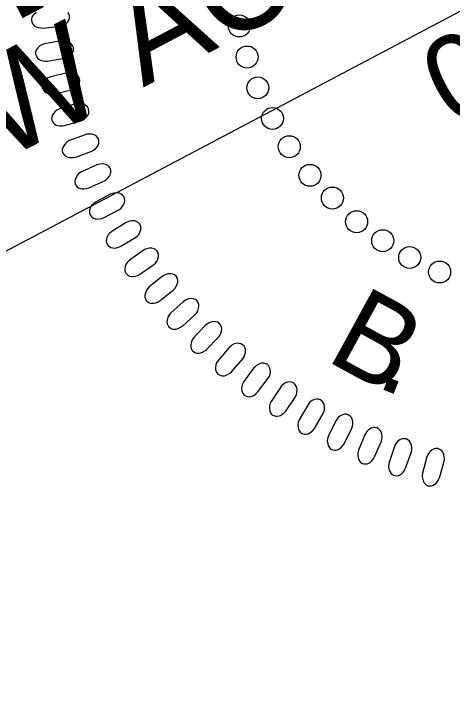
# Model space of a CAD drawing. Extents: x 1486990 to 1489232, y 497582 to 499336.
# Drawn here: x 1488502.11 to 1488528, y 499157.88 to 499198.76 of the extents above; entities that cross this region are included whole.
import ezdxf

# ---------------------------------------------------------------- set-up
doc = ezdxf.new("R2010")
doc.units = 0
doc.layers.add('PROF-MAJR', color=7, linetype='Continuous')
doc.layers.add('Prop Drainage Structure Drop Inlet Adjust CELL', color=7, linetype='Continuous')

msp = doc.modelspace()

# ---------------------------------------------------------------- linework, layer by layer
at = {"layer": 'PROF-MAJR'}
msp.add_lwpolyline([(1488503.435, 499198.848), (1488503.308, 499198.743), (1488503.228, 499198.655), (1488503.174, 499198.558), (1488503.152, 499198.47), (1488503.145, 499198.377), (1488503.171, 499198.289), (1488503.206, 499198.195), (1488503.263, 499198.116), (1488503.352, 499198.041), (1488503.422, 499198), (1488503.548, 499197.959), (1488503.698, 499197.927), (1488503.829, 499197.922), (1488504.841, 499198.027), (1488504.975, 499198.06), (1488505.084, 499198.109), (1488505.204, 499198.194), (1488505.307, 499198.297), (1488505.363, 499198.382), (1488505.398, 499198.514), (1488505.4, 499198.636), (1488505.355, 499198.753), (1488505.305, 499198.833)], dxfattribs=at)
for points in [[(1488504.905, 499197.16), (1488503.926, 499196.99), (1488503.756, 499196.93), (1488503.652, 499196.869), (1488503.532, 499196.757), (1488503.458, 499196.663), (1488503.41, 499196.563), (1488503.393, 499196.474), (1488503.392, 499196.382), (1488503.424, 499196.295), (1488503.464, 499196.204), (1488503.526, 499196.129), (1488503.62, 499196.059), (1488503.693, 499196.022), (1488503.821, 499195.989), (1488503.972, 499195.966), (1488504.103, 499195.97), (1488505.107, 499196.138), (1488505.239, 499196.18), (1488505.344, 499196.235), (1488505.459, 499196.329), (1488505.555, 499196.437), (1488505.606, 499196.526), (1488505.632, 499196.659), (1488505.627, 499196.781), (1488505.574, 499196.895), (1488505.52, 499196.972), (1488505.423, 499197.06), (1488505.271, 499197.132), (1488505.118, 499197.16), (1488505.01, 499197.166)], [(1488505.254, 499195.278), (1488504.288, 499195.047), (1488504.122, 499194.977), (1488504.021, 499194.909), (1488503.909, 499194.789), (1488503.841, 499194.692), (1488503.799, 499194.588), (1488503.788, 499194.499), (1488503.793, 499194.406), (1488503.829, 499194.322), (1488503.876, 499194.233), (1488503.943, 499194.162), (1488504.041, 499194.099), (1488504.115, 499194.066), (1488504.246, 499194.041), (1488504.398, 499194.028), (1488504.528, 499194.04), (1488505.52, 499194.271), (1488505.649, 499194.321), (1488505.751, 499194.382), (1488505.859, 499194.483), (1488505.948, 499194.597), (1488505.993, 499194.689), (1488506.011, 499194.824), (1488505.998, 499194.946), (1488505.938, 499195.056), (1488505.879, 499195.129), (1488505.777, 499195.21), (1488505.621, 499195.273), (1488505.467, 499195.292), (1488505.359, 499195.291)], [(1488505.757, 499193.441), (1488504.807, 499193.15), (1488504.646, 499193.069), (1488504.55, 499192.996), (1488504.445, 499192.868), (1488504.383, 499192.767), (1488504.348, 499192.661), (1488504.342, 499192.571), (1488504.353, 499192.479), (1488504.396, 499192.397), (1488504.447, 499192.311), (1488504.518, 499192.245), (1488504.62, 499192.187), (1488504.696, 499192.16), (1488504.828, 499192.143), (1488504.981, 499192.139), (1488505.11, 499192.16), (1488506.086, 499192.452), (1488506.211, 499192.51), (1488506.309, 499192.578), (1488506.411, 499192.685), (1488506.492, 499192.805), (1488506.531, 499192.899), (1488506.54, 499193.035), (1488506.52, 499193.156), (1488506.454, 499193.262), (1488506.39, 499193.331), (1488506.283, 499193.406), (1488506.123, 499193.459), (1488505.968, 499193.468), (1488505.861, 499193.46)], [(1488506.332, 499191.624), (1488505.402, 499191.274), (1488505.246, 499191.183), (1488505.155, 499191.104), (1488505.059, 499190.97), (1488505.003, 499190.866), (1488504.975, 499190.758), (1488504.974, 499190.667), (1488504.991, 499190.576), (1488505.038, 499190.497), (1488505.095, 499190.415), (1488505.17, 499190.353), (1488505.276, 499190.302), (1488505.354, 499190.279), (1488505.486, 499190.271), (1488505.639, 499190.277), (1488505.767, 499190.305), (1488506.721, 499190.658), (1488506.844, 499190.724), (1488506.936, 499190.798), (1488507.032, 499190.911), (1488507.105, 499191.036), (1488507.138, 499191.133), (1488507.139, 499191.269), (1488507.111, 499191.388), (1488507.038, 499191.489), (1488506.971, 499191.555), (1488506.859, 499191.623), (1488506.696, 499191.665), (1488506.541, 499191.664), (1488506.434, 499191.65)], [(1488507.014, 499189.837), (1488506.108, 499189.43), (1488505.958, 499189.329), (1488505.872, 499189.244), (1488505.784, 499189.105), (1488505.735, 499188.996), (1488505.714, 499188.887), (1488505.719, 499188.796), (1488505.742, 499188.707), (1488505.794, 499188.631), (1488505.856, 499188.552), (1488505.934, 499188.495), (1488506.043, 499188.451), (1488506.122, 499188.433), (1488506.255, 499188.433), (1488506.407, 499188.449), (1488506.532, 499188.485), (1488507.463, 499188.898), (1488507.581, 499188.97), (1488507.669, 499189.05), (1488507.757, 499189.17), (1488507.823, 499189.298), (1488507.85, 499189.397), (1488507.842, 499189.533), (1488507.806, 499189.65), (1488507.727, 499189.747), (1488507.656, 499189.808), (1488507.54, 499189.869), (1488507.375, 499189.9), (1488507.22, 499189.891), (1488507.114, 499189.869)], [(1488507.81, 499188.104), (1488506.931, 499187.64), (1488506.789, 499187.531), (1488506.708, 499187.441), (1488506.629, 499187.296), (1488506.587, 499187.185), (1488506.573, 499187.074), (1488506.584, 499186.985), (1488506.612, 499186.896), (1488506.669, 499186.824), (1488506.735, 499186.75), (1488506.817, 499186.697), (1488506.929, 499186.66), (1488507.008, 499186.647), (1488507.141, 499186.656), (1488507.292, 499186.681), (1488507.415, 499186.725), (1488508.318, 499187.195), (1488508.431, 499187.275), (1488508.514, 499187.36), (1488508.594, 499187.485), (1488508.652, 499187.618), (1488508.672, 499187.718), (1488508.656, 499187.853), (1488508.613, 499187.967), (1488508.528, 499188.059), (1488508.453, 499188.115), (1488508.334, 499188.169), (1488508.167, 499188.19), (1488508.013, 499188.17), (1488507.908, 499188.143)], [(1488508.74, 499186.436), (1488507.892, 499185.918), (1488507.756, 499185.799), (1488507.682, 499185.704), (1488507.612, 499185.555), (1488507.577, 499185.441), (1488507.569, 499185.33), (1488507.586, 499185.241), (1488507.62, 499185.155), (1488507.681, 499185.087), (1488507.753, 499185.016), (1488507.837, 499184.969), (1488507.951, 499184.939), (1488508.031, 499184.931), (1488508.163, 499184.948), (1488508.312, 499184.983), (1488508.432, 499185.034), (1488509.304, 499185.56), (1488509.411, 499185.647), (1488509.488, 499185.737), (1488509.561, 499185.867), (1488509.61, 499186.003), (1488509.625, 499186.104), (1488509.6, 499186.238), (1488509.55, 499186.349), (1488509.459, 499186.436), (1488509.381, 499186.487), (1488509.258, 499186.533), (1488509.091, 499186.544), (1488508.938, 499186.515), (1488508.836, 499186.48)], [(1488509.759, 499184.793), (1488508.945, 499184.223), (1488508.818, 499184.096), (1488508.749, 499183.996), (1488508.689, 499183.843), (1488508.661, 499183.727), (1488508.66, 499183.616), (1488508.683, 499183.528), (1488508.722, 499183.444), (1488508.787, 499183.38), (1488508.862, 499183.314), (1488508.95, 499183.272), (1488509.066, 499183.25), (1488509.147, 499183.247), (1488509.276, 499183.272), (1488509.424, 499183.316), (1488509.54, 499183.375), (1488510.377, 499183.954), (1488510.479, 499184.048), (1488510.55, 499184.143), (1488510.615, 499184.276), (1488510.655, 499184.415), (1488510.663, 499184.517), (1488510.629, 499184.649), (1488510.573, 499184.757), (1488510.477, 499184.838), (1488510.395, 499184.884), (1488510.27, 499184.923), (1488510.102, 499184.923), (1488509.952, 499184.883), (1488509.852, 499184.843)], [(1488510.878, 499183.254), (1488510.102, 499182.633), (1488509.982, 499182.499), (1488509.919, 499182.396), (1488509.869, 499182.238), (1488509.849, 499182.121), (1488509.855, 499182.01), (1488509.883, 499181.924), (1488509.927, 499181.843), (1488509.996, 499181.782), (1488510.076, 499181.722), (1488510.166, 499181.685), (1488510.282, 499181.67), (1488510.363, 499181.672), (1488510.492, 499181.705), (1488510.636, 499181.758), (1488510.748, 499181.825), (1488511.547, 499182.456), (1488511.643, 499182.556), (1488511.708, 499182.655), (1488511.764, 499182.792), (1488511.796, 499182.934), (1488511.797, 499183.035), (1488511.756, 499183.165), (1488511.692, 499183.27), (1488511.592, 499183.344), (1488511.507, 499183.385), (1488511.38, 499183.415), (1488511.212, 499183.405), (1488511.064, 499183.356), (1488510.968, 499183.31)], [(1488512.107, 499181.759), (1488511.371, 499181.091), (1488511.261, 499180.949), (1488511.205, 499180.842), (1488511.164, 499180.682), (1488511.151, 499180.564), (1488511.165, 499180.453), (1488511.198, 499180.369), (1488511.247, 499180.291), (1488511.32, 499180.235), (1488511.403, 499180.179), (1488511.495, 499180.149), (1488511.613, 499180.14), (1488511.693, 499180.148), (1488511.819, 499180.189), (1488511.96, 499180.251), (1488512.067, 499180.324), (1488512.825, 499181.004), (1488512.915, 499181.11), (1488512.974, 499181.213), (1488513.021, 499181.353), (1488513.043, 499181.496), (1488513.038, 499181.598), (1488512.989, 499181.725), (1488512.919, 499181.826), (1488512.814, 499181.893), (1488512.727, 499181.929), (1488512.598, 499181.951), (1488512.432, 499181.93), (1488512.287, 499181.873), (1488512.193, 499181.82)], [(1488513.44, 499180.37), (1488512.748, 499179.658), (1488512.646, 499179.509), (1488512.596, 499179.399), (1488512.566, 499179.237), (1488512.561, 499179.118), (1488512.581, 499179.008), (1488512.619, 499178.926), (1488512.673, 499178.851), (1488512.75, 499178.8), (1488512.836, 499178.75), (1488512.93, 499178.725), (1488513.048, 499178.725), (1488513.127, 499178.737), (1488513.251, 499178.786), (1488513.387, 499178.857), (1488513.49, 499178.936), (1488514.204, 499179.662), (1488514.286, 499179.774), (1488514.339, 499179.88), (1488514.377, 499180.023), (1488514.39, 499180.167), (1488514.379, 499180.269), (1488514.321, 499180.392), (1488514.246, 499180.488), (1488514.137, 499180.549), (1488514.048, 499180.58), (1488513.918, 499180.593), (1488513.753, 499180.562), (1488513.612, 499180.496), (1488513.522, 499180.437)], [(1488514.83, 499179.056), (1488514.183, 499178.301), (1488514.091, 499178.146), (1488514.049, 499178.032), (1488514.029, 499177.869), (1488514.031, 499177.75), (1488514.058, 499177.642), (1488514.101, 499177.563), (1488514.16, 499177.491), (1488514.239, 499177.445), (1488514.329, 499177.4), (1488514.424, 499177.381), (1488514.541, 499177.388), (1488514.62, 499177.405), (1488514.741, 499177.462), (1488514.872, 499177.541), (1488514.97, 499177.627), (1488515.637, 499178.396), (1488515.712, 499178.513), (1488515.758, 499178.622), (1488515.787, 499178.768), (1488515.791, 499178.913), (1488515.774, 499179.013), (1488515.708, 499179.133), (1488515.627, 499179.224), (1488515.514, 499179.278), (1488515.423, 499179.302), (1488515.293, 499179.308), (1488515.13, 499179.266), (1488514.994, 499179.191), (1488514.907, 499179.127)], [(1488516.291, 499177.85), (1488515.694, 499177.055), (1488515.611, 499176.895), (1488515.577, 499176.779), (1488515.567, 499176.615), (1488515.576, 499176.497), (1488515.61, 499176.39), (1488515.658, 499176.314), (1488515.721, 499176.246), (1488515.803, 499176.205), (1488515.896, 499176.166), (1488515.992, 499176.153), (1488516.109, 499176.167), (1488516.186, 499176.189), (1488516.303, 499176.253), (1488516.429, 499176.341), (1488516.521, 499176.433), (1488517.138, 499177.242), (1488517.206, 499177.364), (1488517.245, 499177.475), (1488517.265, 499177.622), (1488517.261, 499177.767), (1488517.236, 499177.867), (1488517.164, 499177.982), (1488517.076, 499178.068), (1488516.96, 499178.114), (1488516.868, 499178.133), (1488516.737, 499178.131), (1488516.578, 499178.079), (1488516.446, 499177.995), (1488516.364, 499177.926)], [(1488517.855, 499176.707), (1488517.308, 499175.877), (1488517.236, 499175.712), (1488517.209, 499175.594), (1488517.209, 499175.43), (1488517.226, 499175.312), (1488517.266, 499175.208), (1488517.319, 499175.135), (1488517.386, 499175.071), (1488517.471, 499175.035), (1488517.566, 499175.002), (1488517.662, 499174.996), (1488517.778, 499175.017), (1488517.854, 499175.044), (1488517.966, 499175.115), (1488518.086, 499175.21), (1488518.173, 499175.308), (1488518.738, 499176.154), (1488518.798, 499176.28), (1488518.829, 499176.394), (1488518.84, 499176.542), (1488518.826, 499176.686), (1488518.796, 499176.783), (1488518.717, 499176.893), (1488518.624, 499176.974), (1488518.505, 499177.013), (1488518.412, 499177.026), (1488518.282, 499177.016), (1488518.126, 499176.954), (1488518, 499176.862), (1488517.922, 499176.788)], [(1488519.468, 499175.659), (1488518.974, 499174.796), (1488518.912, 499174.627), (1488518.893, 499174.508), (1488518.904, 499174.343), (1488518.928, 499174.227), (1488518.975, 499174.126), (1488519.032, 499174.056), (1488519.103, 499173.997), (1488519.19, 499173.966), (1488519.286, 499173.939), (1488519.384, 499173.939), (1488519.497, 499173.967), (1488519.571, 499173.999), (1488519.679, 499174.077), (1488519.793, 499174.179), (1488519.873, 499174.282), (1488520.384, 499175.163), (1488520.436, 499175.291), (1488520.46, 499175.408), (1488520.462, 499175.555), (1488520.439, 499175.699), (1488520.403, 499175.794), (1488520.316, 499175.899), (1488520.219, 499175.973), (1488520.098, 499176.005), (1488520.005, 499176.012), (1488519.875, 499175.993), (1488519.723, 499175.922), (1488519.603, 499175.823), (1488519.53, 499175.744)], [(1488521.129, 499174.728), (1488520.691, 499173.835), (1488520.64, 499173.663), (1488520.627, 499173.543), (1488520.649, 499173.379), (1488520.681, 499173.265), (1488520.734, 499173.167), (1488520.795, 499173.101), (1488520.87, 499173.045), (1488520.958, 499173.02), (1488521.056, 499172.999), (1488521.154, 499173.005), (1488521.265, 499173.041), (1488521.337, 499173.077), (1488521.44, 499173.162), (1488521.547, 499173.271), (1488521.621, 499173.379), (1488522.074, 499174.29), (1488522.119, 499174.421), (1488522.136, 499174.539), (1488522.128, 499174.687), (1488522.096, 499174.828), (1488522.054, 499174.921), (1488521.962, 499175.021), (1488521.86, 499175.089), (1488521.737, 499175.113), (1488521.643, 499175.114), (1488521.515, 499175.087), (1488521.368, 499175.006), (1488521.254, 499174.9), (1488521.186, 499174.817)], [(1488522.847, 499173.911), (1488522.465, 499172.993), (1488522.425, 499172.818), (1488522.42, 499172.697), (1488522.452, 499172.536), (1488522.49, 499172.423), (1488522.549, 499172.329), (1488522.615, 499172.267), (1488522.693, 499172.217), (1488522.783, 499172.197), (1488522.882, 499172.182), (1488522.978, 499172.194), (1488523.088, 499172.237), (1488523.157, 499172.278), (1488523.254, 499172.369), (1488523.354, 499172.484), (1488523.421, 499172.596), (1488523.818, 499173.534), (1488523.853, 499173.668), (1488523.863, 499173.786), (1488523.845, 499173.933), (1488523.805, 499174.073), (1488523.757, 499174.163), (1488523.659, 499174.256), (1488523.553, 499174.318), (1488523.429, 499174.334), (1488523.335, 499174.329), (1488523.208, 499174.294), (1488523.067, 499174.205), (1488522.96, 499174.091), (1488522.898, 499174.004)], [(1488524.598, 499173.215), (1488524.275, 499172.275), (1488524.246, 499172.098), (1488524.249, 499171.977), (1488524.29, 499171.817), (1488524.336, 499171.708), (1488524.401, 499171.617), (1488524.471, 499171.558), (1488524.551, 499171.514), (1488524.643, 499171.5), (1488524.742, 499171.491), (1488524.838, 499171.509), (1488524.944, 499171.559), (1488525.011, 499171.604), (1488525.102, 499171.701), (1488525.195, 499171.822), (1488525.254, 499171.938), (1488525.591, 499172.899), (1488525.618, 499173.035), (1488525.62, 499173.154), (1488525.594, 499173.3), (1488525.545, 499173.436), (1488525.491, 499173.522), (1488525.387, 499173.61), (1488525.277, 499173.664), (1488525.153, 499173.673), (1488525.059, 499173.662), (1488524.935, 499173.62), (1488524.799, 499173.521), (1488524.7, 499173.401), (1488524.644, 499173.31)], [(1488526.514, 499172.598), (1488526.251, 499171.64), (1488526.232, 499171.461), (1488526.243, 499171.34), (1488526.295, 499171.184), (1488526.347, 499171.077), (1488526.417, 499170.991), (1488526.49, 499170.937), (1488526.574, 499170.898), (1488526.665, 499170.889), (1488526.766, 499170.887), (1488526.86, 499170.911), (1488526.963, 499170.967), (1488527.027, 499171.016), (1488527.112, 499171.118), (1488527.197, 499171.246), (1488527.249, 499171.365), (1488527.524, 499172.346), (1488527.543, 499172.483), (1488527.538, 499172.602), (1488527.502, 499172.745), (1488527.445, 499172.878), (1488527.386, 499172.961), (1488527.276, 499173.042), (1488527.163, 499173.09), (1488527.038, 499173.09), (1488526.946, 499173.074), (1488526.825, 499173.024), (1488526.696, 499172.917), (1488526.604, 499172.791), (1488526.553, 499172.696)]]:
    msp.add_lwpolyline(points, close=True, dxfattribs=at)
for centre in [(1488515.43, 499198.049), (1488515.889, 499196.212), (1488516.521, 499194.393), (1488517.389, 499192.584), (1488518.378, 499190.917), (1488519.599, 499189.226), (1488520.928, 499187.884), (1488522.359, 499186.487), (1488523.899, 499185.366), (1488525.494, 499184.373), (1488527.259, 499183.517)]:
    msp.add_circle(centre, 0.649, dxfattribs=at)
at = {"layer": 'Prop Drainage Structure Drop Inlet Adjust CELL'}
msp.add_lwpolyline([(1488425.501, 499144.548), (1488414.528, 499165.329), (1488544.519, 499233.968), (1488555.492, 499213.187)], close=True, dxfattribs=at)

# ---------------------------------------------------------------- texts
at = {"layer": 'PROF-MAJR'}
for s, height, rotation, p in [('053892', 5.0514, 27.8351, (1488528.033, 499191.968)), ('B', 5.051, 331.3665, (1488520.439, 499178.353)), ('.', 5.051, 338.1449, (1488523.372, 499176.792))]:
    msp.add_text(s, height=height, rotation=rotation, dxfattribs=at).set_placement(p)
at = {"layer": 'Prop Drainage Structure Drop Inlet Adjust CELL'}
for s, height, p in [('INCOMPLETE PLANS', 11.52, (1488427.952, 499159.074)), ('DO NOT USE FOR R/W ACQUISITION', 5.76, (1488434.071, 499154.445))]:
    msp.add_text(s, height=height, rotation=27.8351, dxfattribs=at).set_placement(p)

doc.saveas('drawing.dxf')
